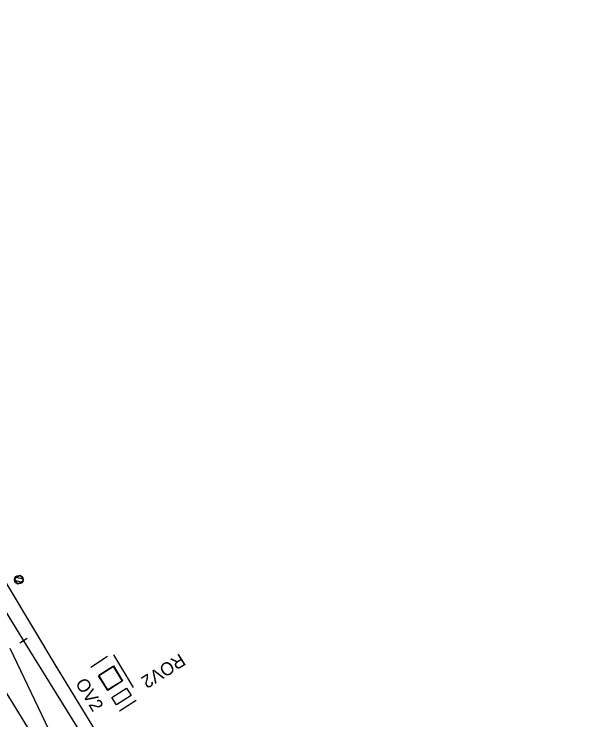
# Model space of a CAD drawing. Extents: x -738085 to -734426, y -1122197 to -1119748.
# Drawn here: x -734534.5 to -734468.7, y -1119936.7 to -1119855.2 of the extents above; entities that cross this region are included whole.
import ezdxf

# ---------------------------------------------------------------- set-up
doc = ezdxf.new("R2010")
doc.units = 0
for name, color, linetype in [('Vrstva 1', 7, 'Continuous'), ('Vrstva 11', 7, 'Continuous'), ('Vrstva 12', 7, 'Continuous'), ('Vrstva 17', 7, 'Continuous'), ('Vrstva 2', 7, 'Continuous'), ('Vrstva 25', 7, 'Continuous'), ('Vrstva 51', 7, 'Continuous')]:
    doc.layers.add(name, color=color, linetype=linetype)

msp = doc.modelspace()

# ---------------------------------------------------------------- linework, layer by layer
at = {"layer": 'Vrstva 1'}
msp.add_line((-734534.968, -1119928.423), (-734529.815, -1119939.218), dxfattribs=at)
msp.add_line((-734534.968, -1119928.423), (-734529.815, -1119939.218), dxfattribs=at)
for points in [[(-734550.425, -1119900.106), (-734547.313, -1119905.141), (-734546.816, -1119905.941), (-734536.98, -1119921.77), (-734536.505, -1119922.557), (-734533.404, -1119927.579)], [(-734550.425, -1119900.106), (-734547.313, -1119905.141), (-734546.816, -1119905.941), (-734536.98, -1119921.77), (-734536.505, -1119922.557), (-734533.404, -1119927.579)], [(-734547.914, -1119913.38), (-734540.826, -1119924.834), (-734532.611, -1119938.087), (-734531.357, -1119940.093)], [(-734547.914, -1119913.38), (-734540.826, -1119924.834), (-734532.611, -1119938.087), (-734531.357, -1119940.093)], [(-734533.404, -1119927.579), (-734527.746, -1119936.717), (-734521.195, -1119947.309), (-734512.704, -1119960.571), (-734505.785, -1119970.119), (-734497.3, -1119980.654), (-734489.154, -1119990.094), (-734476.712, -1120004.556)], [(-734533.404, -1119927.579), (-734527.746, -1119936.717), (-734521.195, -1119947.309), (-734512.704, -1119960.571), (-734505.785, -1119970.119), (-734497.3, -1119980.654), (-734489.154, -1119990.094), (-734476.712, -1120004.556)]]:
    msp.add_lwpolyline(points, dxfattribs=at)
at = {"layer": 'Vrstva 11'}
for p, q in [((-734534.318, -1119920.234), (-734533.429, -1119920.445)), ((-734534.411, -1119920.598), (-734533.509, -1119920.811))]:
    msp.add_line(p, q, dxfattribs=at)
msp.add_circle((-734533.919, -1119920.53), 0.5, dxfattribs=at)
at = {"layer": 'Vrstva 12'}
for points in [[(-734533.792, -1119920.015), (-734533.404, -1119920.657), (-734534.046, -1119921.045), (-734534.434, -1119920.403), (-734533.792, -1119920.015)], [(-734523.021, -1119930.561), (-734521.991, -1119932.26), (-734523.662, -1119933.311), (-734524.727, -1119931.639), (-734523.021, -1119930.561)]]:
    msp.add_lwpolyline(points, dxfattribs=at)
at = {"layer": 'Vrstva 17'}
for p, q in [((-734525.602, -1119930.631), (-734523.677, -1119929.36)), ((-734522.996, -1119929.207), (-734520.709, -1119932.979)), ((-734520.372, -1119934.489), (-734522.302, -1119935.716))]:
    msp.add_line(p, q, dxfattribs=at)
at = {"layer": 'Vrstva 2'}
msp.add_line((-734532.979, -1119927.316), (-734533.829, -1119927.842), dxfattribs=at)
msp.add_lwpolyline([(-734550.425, -1119900.106), (-734547.313, -1119905.141), (-734546.816, -1119905.941), (-734536.98, -1119921.77), (-734536.505, -1119922.557), (-734533.404, -1119927.579)], dxfattribs=at)
at = {"layer": 'Vrstva 25'}
msp.add_lwpolyline([(-734522.989, -1119930.494), (-734521.936, -1119932.195), (-734523.637, -1119933.248), (-734524.69, -1119931.547)], close=True, dxfattribs=at)
msp.add_lwpolyline([(-734521.499, -1119933.053), (-734520.966, -1119933.9), (-734522.659, -1119934.965), (-734523.192, -1119934.118), (-734521.499, -1119933.053)], dxfattribs=at)
at = {"layer": 'Vrstva 51'}
msp.add_lwpolyline([(-734471.461, -1120016.714), (-734468.65, -1120012.126), (-734469.5, -1120009.624), (-734480.395, -1119997.129), (-734492.795, -1119983.479), (-734504.485, -1119969.075), (-734516.903, -1119951.28), (-734529.624, -1119930.533), (-734537.979, -1119916.622), (-734546.25, -1119900.639), (-734552.494, -1119885.802), (-734556.125, -1119875.032), (-734557.76, -1119875.619), (-734561.08, -1119866.636), (-734562.214, -1119867.006), (-734565.536, -1119866.703), (-734569.205, -1119862.802), (-734572.6, -1119856.313), (-734573.268, -1119855.249)], dxfattribs=at)

# ---------------------------------------------------------------- texts
at = {"layer": 'Vrstva 25'}
for s, rotation, p in [('ROV2', 212.16844, (-734515.31, -1119928.99)), ('OV2', 301.76466, (-734527.46, -1119932.48))]:
    msp.add_text(s, height=1.5, rotation=rotation, dxfattribs=at).set_placement(p)

doc.saveas('drawing.dxf')
